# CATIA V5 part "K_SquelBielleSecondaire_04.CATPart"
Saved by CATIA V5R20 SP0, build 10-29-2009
Part number: Squelette_bielle_secondaire_04
Publications: "Droite.1", "Droite.2"
Bounding box of the stored display mesh (mm): x -400 to 0, y -40 to 0, z -150 to -150
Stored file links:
  G:\Khaled_CFAO_2011\ST2M\ST2M_GR2\jcoetard\Khaled\CAD_CATIA\K_SquelBielleSecondaire_04.CATPart
  G:\Khaled_CFAO_2011\ST2M\ST2M_GR2\jcoetard\Khaled\CAD_CATIA\K_Squelette.CATProduct
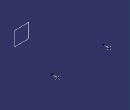
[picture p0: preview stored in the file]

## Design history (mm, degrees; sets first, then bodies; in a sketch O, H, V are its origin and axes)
Set1
  Plane1 "Plan_bielle_secondaire_03": linked copy from another document
  Point1: linked copy from another document
  Point2 "Point.9": linked copy from another document
Set2 "Set géométrique"
  Line1: type Normal, RefPoint Point1, RefSkin Plane1, Start 0, End 40
  Line2: type Normal, RefPoint Point2, RefSkin Plane1, Start 0, End 40
Body1 (main body)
